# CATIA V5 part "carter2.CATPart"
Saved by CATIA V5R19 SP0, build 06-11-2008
Part number: carter2
Bounding box of the stored display mesh (mm): x -64.997 to 64.997, y -75 to 125, z -64.996 to 64.996
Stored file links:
  D:\thinkmotion-MPB\Dropbox\CIAO82010_JCF\BAUVIN\20_bauvin\carter2.CATPart
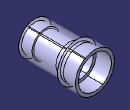
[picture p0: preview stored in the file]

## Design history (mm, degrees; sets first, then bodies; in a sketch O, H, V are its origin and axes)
Set1
  Point1: type Center, Curve edge [face of Shaft1 from Sketch1.L9 | face of Shaft1 from Sketch1.L8]
  Line1: type Normal, RefPoint Point1, RefSkin face of Shaft1 from Sketch1.L9, Start 0, End 20
Body1 (main body)
  Sketch1 on yz-plane, origin (0, 0, 0), H (0, 1, 0), V (0, 0, 1)
    line L1 (-75, 55) -> (-75, 45)
    line L2 (-75, 45) -> (-40, 45)
    line L3 (-40, 45) -> (-40, 40)
    line L4 (-40, 40) -> (40, 40)
    line L5 (40, 40) -> (40, 45)
    point P6 (40, 45)
    line L6 (40, 45) -> (75, 45)
    line L7 (75, 45) -> (75, 55)
    line L8 (75, 55) -> (125, 55)
    line L9 (125, 55) -> (125, 65)
    line L10 (125, 65) -> (65, 65)
    line L11 (65, 65) -> (65, 55)
    line L12 (65, 55) -> (-75, 55)
    distance L12 L2 = 10
    distance L12 L4 = 15
    distance L8 L10 = 10
    distance L11 L7 = 10
    length L6 = 35
    length L2 = 35
    length L4 = 80
    distance L8 L6 = 10
    length L10 = 60
    distance L4 H = 40
    vertical: L1 V, L3 V, L5 V, L7 V, L9 V, L11 V
    horizontal: L2 H, L4 H, L6 H, L8 H, L10 H
    coincidence: P6 L2
    symmetry: L3 L5 V
  Shaft1: profile Sketch1, axis Sketch1.H, angle 360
